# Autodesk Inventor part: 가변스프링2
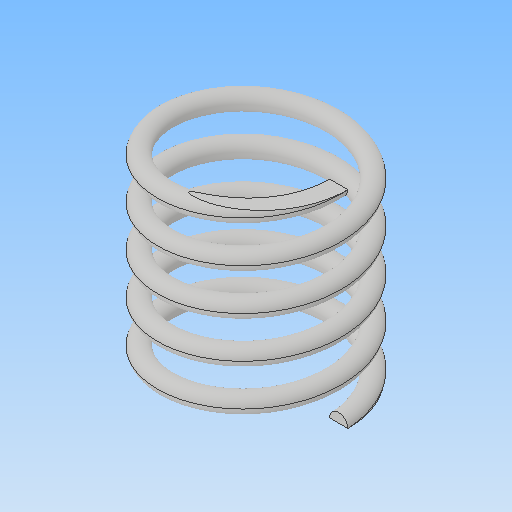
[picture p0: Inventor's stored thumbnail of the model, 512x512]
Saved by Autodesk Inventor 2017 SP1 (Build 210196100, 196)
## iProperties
Part Number: 가변스프링2
Material: 일반
Document SubType Name: Modeling
Designer: MRC
Density: 1 g/cm^3
Appearance: 기본값
Author: MRC
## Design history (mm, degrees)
sketch "스케치1"
  geometry: L1 (0, 0)-(0, 22.5); L2 (0, 0)-(9, 0); L3 (0, 22.5)-(9, 22.5); C1 r 1 at (9, 0)
  constraints: 6 end point, 1 centre point, 1 coincident, 1 parallel, 1 perpendicular, 1 vertical
  dimensions: "d0" = 22.5 distance of L1.start L1.end (derived); "d1" = 9 distance of L1.start L2.end; "d2" = 9 distance of L1.end L3.end; "d3" = 2 diameter of C1
feature "코일1" sketch "스케치1" pitch "d4" = 10; turns "d6" = 5; dims "d5" = 22.5 (= d0), "d7" = 0, angle "d8" = 90 deg, angle "d9" = 90 deg, "d10" = 0, "d11" = 0
sketch "스케치2"
  geometry: L1 (22.5, 20)-(0, 20); L2 (0, 20)-(0, -20); L3 (0, -20)-(22.5, -20); L4 (22.5, -20)-(22.5, 20); 2 further points
  constraints: 8 end point, 2 parallel, 1 coincident, 1 horizontal, 1 midpoint, 1 perpendicular
  dimensions: "d12" = 40 distance of L3.end L1.start; "d13" = 22.5 distance of L2.end L3.end (= d0)
extrude "돌출1" sketch "스케치2" stored distance "d14" = 0; taper "d15" = 0 deg
node "솔리드1"
